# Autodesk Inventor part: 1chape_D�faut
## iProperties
Created: 2011-01
Part Number: 1chape_D�faut
Document SubType Name: Modeling
Designer: eric
Density: 1 g/cm^3
Mass: 45.1239 g
Surface Area: 242.195 cm^2
Volume: 45.1239 cm^3
Author: eric
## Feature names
1. Base1
